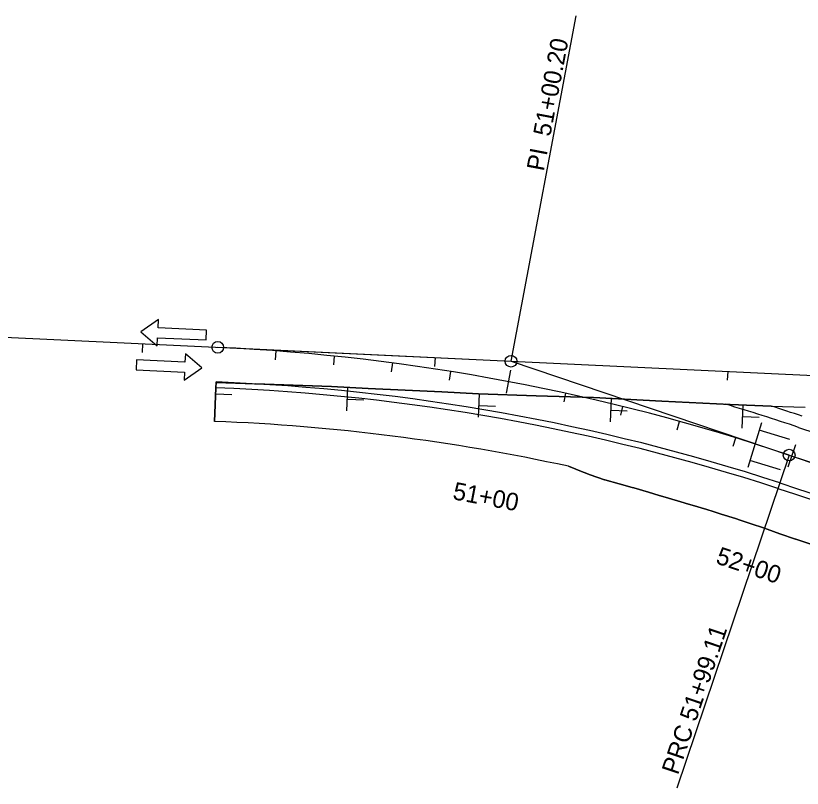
# Model space of a CAD drawing. Extents: x 1140339 to 1165793, y 1646213 to 1669071.
# Drawn here: x 1148790.2 to 1149058.7, y 1657344.4 to 1657608 of the extents above; entities that cross this region are included whole.
import ezdxf

# ---------------------------------------------------------------- set-up
doc = ezdxf.new("R2010")
doc.units = 0
for name, color, linetype in [('R_Horz Alg', 7, 'Continuous'), ('R_Horz Alg Annot', 7, 'Continuous'), ('R_MOT', 7, 'Continuous'), ('R_No Plot', 7, 'Continuous'), ('R_Proposed Const Limits_Fill', 7, 'Continuous'), ('R_Proposed Road_Lane', 7, 'Continuous'), ('R_Proposed Road_Shoulder', 7, 'Continuous')]:
    doc.layers.add(name, color=color, linetype=linetype)

msp = doc.modelspace()

# ---------------------------------------------------------------- linework, layer by layer
at = {"layer": 'R_Horz Alg'}
msp.add_line((1148434, 1657515.04), (1150132.09, 1657434.46), dxfattribs=at)
for centre, start, end in [((1148825.2, 1656779.47), 71.35438, 87.28333), ((1149283.16, 1658136.69), 251.35438, 283.21228)]:
    msp.add_arc(centre, 716.2, start, end, dxfattribs=at)
at = {"layer": 'R_Horz Alg Annot'}
for p, q in [((1148859.15, 1657494.87), (1148959.24, 1657490.12)), ((1148959.24, 1657490.12), (1149054.18, 1657458.08)), ((1149054.18, 1657458.08), (1149247.86, 1657392.73))]:
    msp.add_line(p, q, dxfattribs=at)
for points in [[(1148959.24, 1657490.12), (1148981.48, 1657608.04)], [(1148833.4, 1657493.08), (1148833.55, 1657496.08)], [(1148878.88, 1657490.65), (1148879.11, 1657493.64)], [(1148898.72, 1657488.87), (1148899.03, 1657491.86)], [(1148918.5, 1657486.54), (1148918.89, 1657489.52)], [(1148933.29, 1657488.34), (1148933.43, 1657491.34)], [(1148959.12, 1657487.11), (1148957.63, 1657479.25)], [(1148938.2, 1657483.66), (1148938.68, 1657486.62)], [(1149033.18, 1657483.61), (1149033.32, 1657486.6)], [(1148977.34, 1657476.26), (1148977.98, 1657479.19)], [(1148996.73, 1657471.74), (1148997.45, 1657474.65)], [(1149015.99, 1657466.68), (1149016.8, 1657469.57)], [(1149035.11, 1657461.08), (1149035.99, 1657463.95)], [(1149056.29, 1657461.59), (1149053.75, 1657454.01)], [(1149054.18, 1657458.08), (1149015.81, 1657344.38)]]:
    msp.add_lwpolyline(points, dxfattribs=at)
for centre in [(1148859.15, 1657494.87), (1148959.24, 1657490.12), (1149054.18, 1657458.08)]:
    msp.add_circle(centre, 2, dxfattribs=at)
at = {"layer": 'R_MOT'}
for p, q in [((1148858.25, 1657475.04), (1148858.58, 1657483.04)), ((1148858.53, 1657479.02), (1148863.99, 1657478.79)), ((1148903.25, 1657473.23), (1148903.58, 1657481.22)), ((1148948.19, 1657471.05), (1148948.52, 1657479.05)), ((1148903.53, 1657477.2), (1148908.98, 1657476.97)), ((1148993.16, 1657469.42), (1148993.49, 1657477.42)), ((1148948.47, 1657475.02), (1148953.93, 1657474.8)), ((1148993.44, 1657473.4), (1148998.89, 1657473.17)), ((1149038.15, 1657467.26), (1149038.48, 1657475.26)), ((1149038.43, 1657471.24), (1149043.89, 1657471.01)), ((1149044.72, 1657469.11), (1149040.05, 1657453.8)), ((1149054.39, 1657463.4), (1149043.95, 1657466.58)), ((1149051.22, 1657453.01), (1149040.78, 1657456.2))]:
    msp.add_line(p, q, dxfattribs=at)
for points in [[(1148838.9, 1657504.33), (1148832.85, 1657500.11), (1148838.47, 1657495.34), (1148838.6, 1657498.15), (1148855.14, 1657497.37), (1148855.3, 1657500.74), (1148838.76, 1657501.52)], [(1148847.66, 1657483.63), (1148853.71, 1657487.85), (1148848.09, 1657492.62), (1148847.96, 1657489.82), (1148831.42, 1657490.6), (1148831.26, 1657487.23), (1148847.8, 1657486.44)]]:
    msp.add_lwpolyline(points, close=True, dxfattribs=at)
at = {"layer": 'R_No Plot'}
for p, q in [((1148858.51, 1657481.04), (1148858.58, 1657482.88)), ((1148858.07, 1657469.58), (1148858.51, 1657481.04))]:
    msp.add_line(p, q, dxfattribs=at)
for points in [[(1148858.58, 1657482.88), (1148897.96, 1657481.47), (1148910.52, 1657480.86), (1148923.08, 1657480.25), (1148935.64, 1657479.65), (1148948.19, 1657479.04), (1148967.8, 1657478.37), (1148987.41, 1657477.7), (1149010.75, 1657476.54), (1149034.09, 1657475.38), (1149048.03, 1657474.84)], [(1149048.03, 1657474.84), (1149059.68, 1657474.4)], [(1149061.58, 1657427.64), (1149056.41, 1657429.39), (1149056.29, 1657429.43), (1149051.02, 1657431.27), (1149046.64, 1657432.85), (1149045.77, 1657433.16), (1149045.77, 1657433.16), (1149040.85, 1657434.79), (1149037.43, 1657435.9), (1149035.92, 1657436.4), (1149030.98, 1657437.97), (1149028.25, 1657438.82), (1149026.03, 1657439.5), (1149021.07, 1657441), (1149019.03, 1657441.61), (1149018.33, 1657441.82), (1149016.09, 1657442.47), (1149011.11, 1657443.9), (1149009.78, 1657444.3), (1149006.14, 1657445.39), (1149001.17, 1657446.86), (1149000.54, 1657447.05), (1148996.19, 1657448.3), (1148991.27, 1657449.68), (1148991.19, 1657449.7), (1148986.25, 1657451.34), (1148982.14, 1657452.98), (1148981.37, 1657453.28), (1148978.85, 1657454.26)]]:
    msp.add_lwpolyline(points, dxfattribs=at)
msp.add_arc((1148831.73, 1656778.24), 691.84, 77.72262, 87.81824, dxfattribs=at)
at = {"layer": 'R_Proposed Const Limits_Fill'}
msp.add_line((1148858.51, 1657481.04), (1148858.07, 1657469.58), dxfattribs=at)
for points in [[(1149048.03, 1657474.84), (1149059.68, 1657474.4)], [(1148978.85, 1657454.26), (1148981.37, 1657453.28), (1148982.14, 1657452.98), (1148986.25, 1657451.34), (1148991.19, 1657449.7), (1148991.27, 1657449.68), (1148996.19, 1657448.3), (1149000.54, 1657447.05), (1149001.17, 1657446.86), (1149006.14, 1657445.39), (1149009.78, 1657444.3), (1149011.11, 1657443.9), (1149016.09, 1657442.47), (1149018.33, 1657441.82), (1149019.03, 1657441.61), (1149021.07, 1657441), (1149026.03, 1657439.5), (1149028.25, 1657438.82), (1149030.98, 1657437.97), (1149035.92, 1657436.4), (1149037.43, 1657435.9), (1149040.85, 1657434.79), (1149045.77, 1657433.16), (1149045.77, 1657433.16), (1149046.64, 1657432.85), (1149051.02, 1657431.27), (1149056.29, 1657429.43), (1149056.41, 1657429.39), (1149061.58, 1657427.64)]]:
    msp.add_lwpolyline(points, dxfattribs=at)
msp.add_arc((1148831.73, 1656778.24), 691.84, 77.72262, 87.81824, dxfattribs=at)
at = {"layer": 'R_Proposed Road_Lane'}
msp.add_line((1148858.58, 1657483.04), (1148858.51, 1657481.04), dxfattribs=at)
msp.add_lwpolyline([(1149048.03, 1657474.84), (1149034.09, 1657475.38), (1149010.75, 1657476.54), (1148987.41, 1657477.7), (1148967.8, 1657478.37), (1148948.19, 1657479.04), (1148935.64, 1657479.65), (1148923.08, 1657480.25), (1148910.52, 1657480.86), (1148897.96, 1657481.47), (1148871.87, 1657482.41)], dxfattribs=at)
for centre, radius, start, end in [((1148831.73, 1656778.24), 705.31, 71.88929, 87.81824), ((1148825.2, 1656779.47), 726.2, 71.35438, 73.40781), ((1149283.16, 1658136.69), 706.2, 251.35438, 283.21228), ((1149283.16, 1658136.69), 726.2, 251.35438, 283.21228)]:
    msp.add_arc(centre, radius, start, end, dxfattribs=at)
at = {"layer": 'R_Proposed Road_Shoulder'}
for centre, radius, start, end in [((1148831.73, 1656778.24), 703.31, 71.88929, 87.81824), ((1148825.2, 1656779.47), 730.2, 71.35438, 72.23213), ((1149283.16, 1658136.69), 728.2, 251.35438, 283.21228)]:
    msp.add_arc(centre, radius, start, end, dxfattribs=at)

# ---------------------------------------------------------------- texts
at = {"layer": 'R_Horz Alg Annot'}
for s, rotation, p in [('PI  51+00.20', 79.3189, (1148970.41, 1657554.76)), ('51+00', 349.2833, (1148939.08, 1657443.07)), ('52+00', 341.4254, (1149028.81, 1657421.24)), ('PRC 51+99.11', 71.3544, (1149016.21, 1657348.68))]:
    msp.add_text(s, height=6, rotation=rotation, dxfattribs=at).set_placement(p)

doc.saveas('drawing.dxf')
